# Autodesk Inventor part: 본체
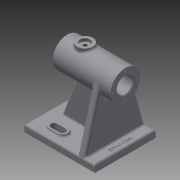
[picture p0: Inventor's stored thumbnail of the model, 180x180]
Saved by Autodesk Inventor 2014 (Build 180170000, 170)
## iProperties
Created: 2019-10
Part Number: 본체
Material: Generic
Document SubType Name: Modeling
Designer: kh
Density: 1 g/cm^3
Appearance: Default
Author: kh
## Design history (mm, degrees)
sketch "Sketch1"
  geometry: L1 (-50, -43)-(50, -43); L2 (50, -43)-(50, 43); L3 (50, 43)-(-50, 43); L4 (-50, 43)-(-50, -43); L5 (-50, -43)-(50, 43); L6 (50, -43)-(-50, 43); 1 further point
  constraints: 12 end point, 2 midpoint, 2 parallel, 1 horizontal, 1 perpendicular
  dimensions: "d0" = 100 distance of L3.end L2.end; "d1" = 86 distance of L2.end L1.end
extrude "Extrusion1" new body sketch "Sketch1" distance "d2" = 10; taper "d3" = 0 deg
sketch "Sketch2"
  geometry: L1 (32, 86)-(-50, 86); L2 (-50, 86)-(-50, 107); L3 (-50, 107)-(32, 107); L4 (32, 107)-(32, 86); L5 (-50, 0)-(50, 0) reference; L6 (-50, 0)-(-50, 10) reference; L7 (32, 100.5)-(-30, 100.5); L8 (-30, 100.5)-(-30, 97.5); L9 (-30, 97.5)-(-50, 97.5); 1 further point
  constraints: 14 end point, 3 perpendicular, 2 parallel, 2 point on line, 1 collinear, 1 horizontal
  dimensions: "d4" = 86 distance between parallel lines of L1 L5; "d5" = 42 diameter of L3 L1; "d6" = 82 distance between parallel lines of L2 L4; "d8" = 29 diameter of L7 L1; "d9" = 23 diameter of L9 L1; "d10" = 62 distance between parallel lines of L4 L8
revolve "Revolution1" stored, may be unused: angle "d7" = 90 deg
revolve "Revolution2" stored, may be unused: angle "d11" = 90 deg
workplane "Work Plane1"
sketch "Sketch3"
  geometry: L1 (-32, 21)-(-32, -21) reference; C1 r 11 at (-7, 0); 1 further point
  constraints: 1 centre point, 1 horizontal alignment
  dimensions: "d13" = 22 diameter of C1; "d14" = 25 distance from line of C1.centre L1
extrude "Extrusion2" join sketch "Sketch3" stored distance "d15" = 13; taper "d16" = 0 deg
fillet "Fillet3" dims "d53" = 3
workplane "Work Plane2"
sketch "Sketch8"
  geometry: L1 (0, 86)-(7, 86) reference; L2 (0, 0)-(7, 0) reference; L3 (10, 83)-(10, 3) reference; L4 (7.783, 85.896)-(91.48, 63.272); L5 (7.783, 0.104)-(91.48, 22.728); A1 r 21 centre (86, 43) between (91.48, 63.272) and (91.48, 22.728) reference; A2 r 3 centre (7, 83) between (10, 83) and (7, 86) reference; A3 r 3 centre (7, 3) between (7, 0) and (10, 3) reference; A4 r 21 centre (86, 43) between (91.48, 63.272) and (91.48, 22.728); A5 r 3 centre (7, 83) between (10, 83) and (7.783, 85.896); A6 r 3 centre (7, 3) between (7.783, 0.104) and (10, 3); 1 further point
  constraints: 10 point on circle, 4 end point, 4 tangent, 3 centre point, 3 coincident
extrude "Extrusion4" join sketch "Sketch8" distance "d22" = 10; taper "d23" = 0 deg
sketch "Sketch9"
  geometry: L1 (35, 10)-(23.08, 42.749); L2 (50, 0)-(50, 7) reference; L3 (47, 10)-(-25, 10) reference; 1 further point
  constraints: 2 end point, 1 point on line
  dimensions: "d55" = 15 distance from line of L1.start L2; "d56" = 70 deg angle of L3 L1
feature "Rib1" sketch "Sketch9" dims "d26" = 1, "d27" = 10, "d28" = 0, "d29" = 0, "d30" = 1, "d31" = 1
workplane "Work Plane3"
sketch "Sketch10"
  geometry: L1 (-24, 27)-(-12, 27); L2 (-24, 20)-(-12, 20); L3 (-12, 34)-(-24, 34); L4 (0, 0)-(-50, 0); L5 (-50, 43)-(-50, -43) reference; A1 r 7 centre (-24, 27) between (-24, 34) and (-24, 20); A2 r 7 centre (-12, 27) between (-12, 20) and (-12, 34); 1 further point
  constraints: 10 end point, 4 point on circle, 4 tangent, 2 centre point, 1 horizontal, 1 midpoint, 1 parallel
  dimensions: "d33" = 12 distance of L1.start L1.end; "d34" = 14 distance between parallel lines of L2 L3; "d36" = 27 distance between parallel lines of L4 L1; "d54" = 26 distance from line of L1.start L5
extrude "Extrusion5" join sketch "Sketch10" stored distance "d37" = 10; taper "d38" = 0 deg
sketch "Sketch11"
  geometry: L1 (-24, 34)-(-12, 34) reference; L2 (-12, 20)-(-24, 20) reference; L3 (-12, 31.5)-(-24, 31.5); L4 (-24, 22.5)-(-12, 22.5); A1 r 7 centre (-24, 27) between (-24, 34) and (-24, 20) reference; A2 r 7 centre (-12, 27) between (-12, 20) and (-12, 34) reference; A3 r 4.5 centre (-24, 27) between (-24, 31.5) and (-24, 22.5); A4 r 4.5 centre (-12, 27) between (-12, 22.5) and (-12, 31.5); 1 further point
  constraints: 4 end point, 4 point on circle, 2 centre point, 3 other
  dimensions: "d39" = 9 distance between parallel lines of L4 L3
extrude "Extrusion6" cut sketch "Sketch11" stored distance "d40" = 10; taper "d41" = 0 deg
fillet "Fillet1" dims "d42" = 3
mirror "Mirror1"
hole "Hole1" diameter "d45" = 5.242; stored, may be unused: countersink angle "d49" = 90 deg, drill point angle "d51" = 118 deg; dims "d43" = 10, "d44" = 10, "d46" = 6, "d47" = 14, "d48" = 4, "d50" = 8
fillet "Fillet4" dims "d57" = 3
fillet "Fillet5" dims "d58" = 3
sketch "Sketch13"
  geometry: C1 r 21 at (0, 0) reference; 2 further points
  constraints: 1 vertical alignment
  dimensions: "d59" = 18 distance of point (0, 18) C1.centre
hole "Hole2" sketch "Sketch13" at (0, 18) diameter "d60" = 2.459; stored, may be unused: countersink angle "d64" = 90 deg, drill point angle "d66" = 118 deg; dims "d61" = 8, "d62" = 14, "d63" = 4, "d65" = 10
pattern_circular "Circular Pattern1" dims angle "d68" = 360 deg
sketch "Sketch14"
  geometry: C1 r 21 at (0, 0) reference; 2 further points
  constraints: 1 horizontal alignment
  dimensions: "d70" = 18 distance of point (18, 0) C1.centre
hole "Hole3" sketch "Sketch14" at (18, 0) diameter "d71" = 2.459; stored, may be unused: countersink angle "d75" = 90 deg, drill point angle "d77" = 118 deg; dims "d72" = 8, "d73" = 14, "d74" = 4, "d76" = 10
pattern_circular "Circular Pattern2" dims angle "d79" = 360 deg
chamfer "Chamfer1" distance "d81" = 1; stored, may be unused: second distance "d82" = 2, angle "d83" = 45 deg
sketch "Sketch15"
  geometry: L1 (40.598, -16.592)-(40.598, 16.592); L2 (40.598, 16.592)-(45.402, 16.592); L3 (45.402, 16.592)-(45.402, -16.592); L4 (45.402, -16.592)-(40.598, -16.592); L5 (45.402, -16.592)-(40.598, 16.592); L6 (50, -43)-(50, 43) reference; 2 further points
  constraints: 2 end point, 1 horizontal alignment, 1 midpoint, 2 other
  dimensions: "d84" = 7 distance from line of L6 point (43, 0)
emboss "Emboss1" sketch "Sketch15" dims "d0" = 100, "d1" = 86, "d85" = 0.5, "d86" = 0
fillet "Fillet6" dims "d87" = 3
fillet "Fillet7" dims "d88" = 3
body "Solid1"
other parameters: "d21" = -75, "d32" = 13
